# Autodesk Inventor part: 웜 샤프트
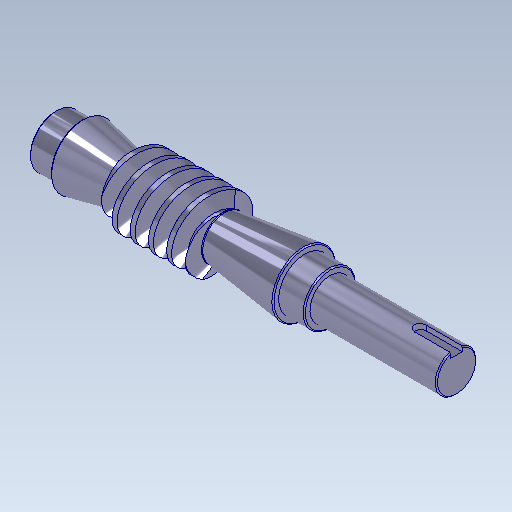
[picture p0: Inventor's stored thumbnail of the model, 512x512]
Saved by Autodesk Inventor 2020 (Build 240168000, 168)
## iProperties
CustomPartVersion: 1
Created: 2013-01
Part Number: 웜 샤프트
Material: 탄소강
Document SubType Name: Modeling
Designer: 한국산업디자인학원[gmhk.co.kr]
Categories: <?xml version="1.0" encoding="UTF-16"?> <MemberInstance><Categories><FamilyTemplate><FamilyTemplateParameter ValueType="xs:double" Id="1" ObjectReferenceKey="da
Density: 7.87 g/cm^3
Mass: 4106.37 g
Surface Area: 646.884 cm^2
Volume: 521.775 cm^3
Appearance: _시험-파란색 크롬
Author: 한국산업디자인학원[gmhk.co.kr]
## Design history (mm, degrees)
body "Solid1"
extrude "기본 본체" new body stored distance "d6" = 80 (= da_b); taper "d7" = 0 deg
chamfer "Chamfer1" distance "d8" = 4.00367 (= fd_cham1); stored, may be unused: second distance "d9" = 11 (= 0.5 x fd_cham2), angle "d47" = 45 deg
chamfer "Chamfer2" distance "d10" = 4.00367 (= fd_cham1); stored, may be unused: second distance "d11" = 11 (= 0.5 x fd_cham2), angle "d48" = 45 deg
sketch "톱니 스케치"
  geometry: L1 (0, 21.74)-(0, 10.96) reference; L2 (-60.834, 30.3)-(-56.721, 19); L3 (-53.235, 19)-(-49.122, 30.3); L4 (-50.535, 0)-(-37.455, 0) reference; L5 (-60.834, 30.3)-(-54.978, 30.3); L6 (-54.978, 30.3)-(-49.122, 30.3); L7 (-56.721, 19)-(-54.978, 19); L8 (-54.978, 19)-(-53.235, 19); L9 (-54.978, 25)-(-51.051, 25); L10 (-54.978, 30.3)-(-54.978, 19)
  constraints: 16 end point, 3 equal length, 3 parallel, 2 collinear, 2 point on line
  dimensions: "d24" = 110 deg angle of L7 L2 (computed from da_alfat); "d25" = 54.97787 distance from line of L1 L5.end (= fd_dist); "d26" = 3.92699 distance of L9.start L9.end (= 0.25 x da_px); "d27" = 19 distance between parallel lines of L4 L7 (= 0.5 x da_df); "d28" = 25 distance between parallel lines of L4 L9 (= 0.5 x da_d); "d29" = 30.3 distance between parallel lines of L4 L5 (= 0.505 x da_da)
feature "톱니" pitch "d30" = 31.41593 (computed from da_px, da_z); turns "d32" = 8 (= fd_n); dims "d31" = 10, "d33" = 0, angle "d34" = 90 deg, angle "d35" = 90 deg, "d36" = 0, "d37" = 0, "d70" = 10, "da_rightdir" = 0 [user parameter]
pattern_circular "톱니 패턴" dims angle "d46" = 360 deg, "da_rightdir" = 0 [user parameter]
feature "왼쪽 톱니" pitch "d62" = 31.41593 (computed from da_px, da_z); turns "d64" = 8 (= fd_n); dims "d63" = 10, "d65" = 0, angle "d66" = 90 deg, angle "d67" = 90 deg, "d68" = 0, "d69" = 0, "d76" = 10, "da_rightdir" = 0 [user parameter]
pattern_circular "왼쪽 톱니 패턴" dims angle "d73" = 360 deg, "da_rightdir" = 0 [user parameter]
sketch "스케치8"
  geometry: C1 r 18.99 at (0, 0); A1 r 19 centre (0, 0) between (9.02, 16.723) and (-3.823, 18.611) reference; A2 r 19 centre (0, 0) between (-3.823, 18.611) and (-9.02, -16.723) reference; A3 r 19 centre (0, 0) between (-9.02, -16.723) and (3.823, -18.611) reference; A4 r 19 centre (0, 0) between (3.823, -18.611) and (9.02, 16.723) reference; 1 further point
  constraints: 1 centre point, 1 coincident
  dimensions: "d87" = 0.01 radial gap between concentric circles of C1 A2
node "작업 평면10"
extrude "돌출2" join sketch "스케치8" distance "d88" = 1; taper "d89" = 0 deg
mirror "대칭1"
revolve "회전1" stored, may be unused: angle "d90" = 90 deg
chamfer "모따기3" distance "d91" = 1; stored, may be unused: second distance "d92" = 2, angle "d93" = 45 deg
node "작업 평면11"
sketch "스케치9"
  geometry: L1 (-54.5, -16.5)-(-54.5, 16.5) reference; L2 (-54.5, 5)-(-23.5, 5); L3 (-23.5, -5)-(-54.5, -5); A1 r 5 centre (-23.5, 0) between (-23.5, -5) and (-23.5, 5); 2 further points
  constraints: 4 end point, 2 perpendicular, 2 point on circle, 2 point on line, 2 tangent, 1 centre point, 1 horizontal alignment, 1 midpoint
  dimensions: "d94" = 10 distance between parallel lines of L3 L2; "d96" = 36 dimension on A1 L1
extrude "돌출3" cut sketch "스케치9" distance "d97" = 5; taper "d98" = 0 deg
node "기본 본체 스케치" dims "d5" = 60 (= da_da)
sketch "Sketch5"
  geometry: C1 r 30 at (0, 0) reference; C2 r 25 at (0, 0)
  constraints: 1 centre point, 1 coincident
  dimensions: "d59" = 50 diameter of C2 (= da_d)
body "Srf1"
sketch "스케치7" dims "d5" = 60 (= da_da)
  geometry: L1 (40, 18.611)-(40, -16.723) reference; L2 (40, 19)-(40, 16.723) reference; L3 (40, 18.611)-(40, 16.723) reference; L4 (40, -16.723)-(40, 18.611) reference; L5 (40, -18.611)-(40, -16.723) reference; L6 (40, 16.723)-(40, -18.611) reference; L7 (40, -16.723)-(40, -19) reference; L8 (41, 0)-(241, 0); L9 (110, 27.5)-(110, 22.5); L10 (110, 22.5)-(132, 22.5); L11 (132, 22.5)-(132, 17.5); L12 (132, 17.5)-(241, 17.5); L13 (241, 17.5)-(241, 0); L14 (127.9, 22.5)-(111.1, 22.5) reference; L15 (110, -41.4)-(110, 41.4) reference; L16 (-40, -16.723)-(-40, 18.611) reference; L17 (-41, 0)-(-105, 0); L18 (25.305, 19)-(-40, 19) reference; L19 (-82, 27.5)-(-82, 22.5); L20 (-82, 22.5)-(-105, 22.5); L21 (-105, 22.5)-(-105, 0); L22 (-82, 41.4)-(-82, -41.4) reference; L23 (41, 18.99)-(41, -18.99) reference; L24 (41, 0)-(41, 18.99); L25 (41, 18.99)-(110, 27.5); L26 (-41, 18.99)-(-41, -18.99) reference; L27 (-41, 0)-(-41, 18.99); L28 (-41, 18.99)-(-82, 27.5); 1 further point
  constraints: 30 end point, 7 collinear, 7 perpendicular, 2 midpoint, 1 horizontal, 1 horizontal alignment, 1 parallel, 1 point on line, 2 other
  dimensions: "d82" = 35 diameter of L12 L8; "d83" = 55 diameter of L9.start L8; "d84" = 22 distance of L9.end L10.end; "d85" = 200 distance of L8.start L8.end; "d86" = 64 distance of L17.start L17.end
node "투영된 루프1"
node "참조1"
node "참조2"
node "투영된 루프2"
feature "피치 지름" dims "d60" = 10, "d61" = 0
other parameters: "da_b" = 80 [user parameter; used in 3 equation terms], "da_df" = 38 [user parameter; used in 2 equation terms], "fd_cham2" = 22 (= da_da - da_df) [user parameter; used in 3 equation terms], "fd_cham1" = 4.00367 (= 0.181985 x fd_cham2) [user parameter; used in 2 equation terms], "da_d" = 50 [user parameter; used in 2 equation terms], "da_px" = 90 deg [user parameter; used in 5 equation terms], "fd_dist" = 54.97787 (computed from da_b, da_px) [user parameter; used in 1 equation term], "fd_n" = 8 (computed from da_b, da_px) [user parameter; used in 2 equation terms], "da_alfat" = 20 deg [user parameter; used in 1 equation term], "d12" = 110 deg (derived), "d14" = 3.1425 (derived), "d50" = 0, "d54" = 0, "d56" = 0, "d77" = 0, "d80" = 0
